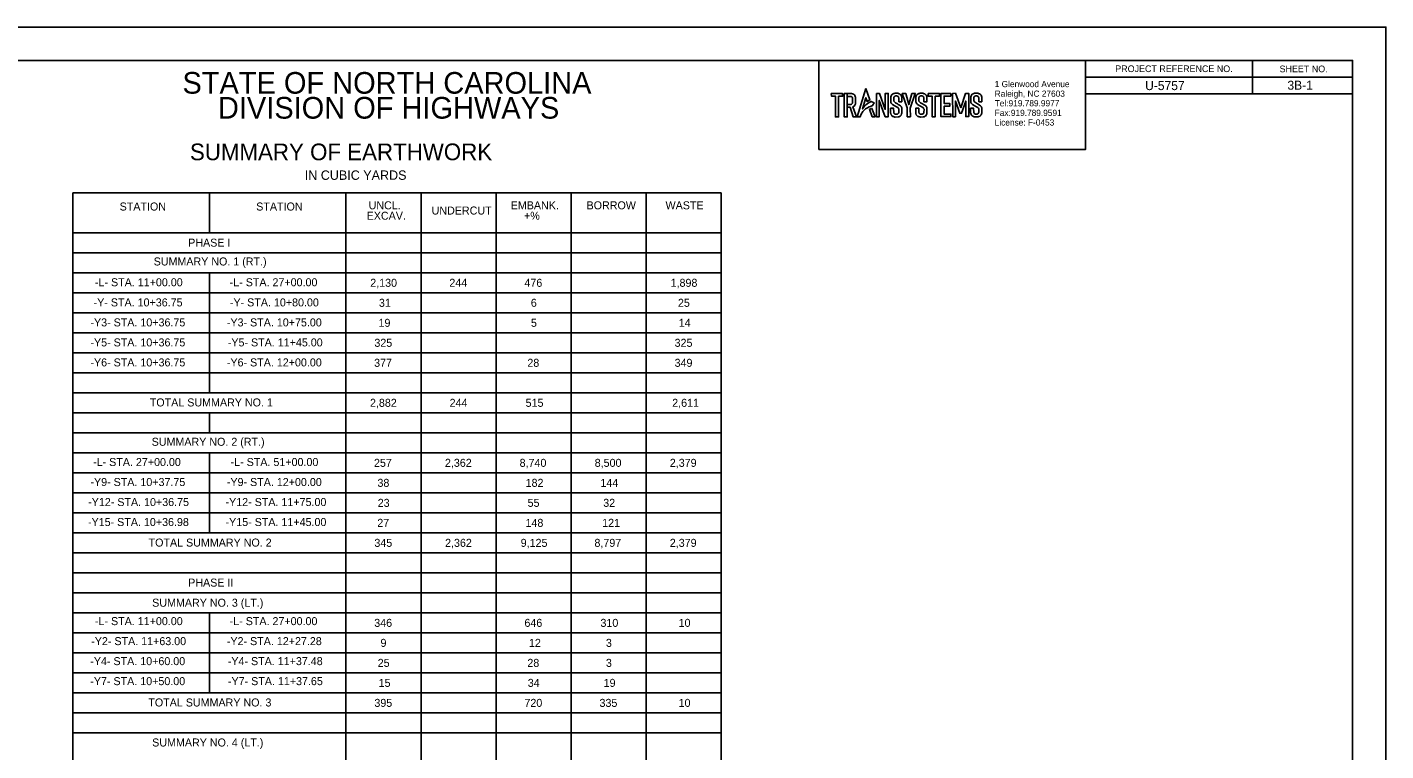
# Model space of a CAD drawing. Extents: x 573680 to 575380, y -53324 to -52224.
# Drawn here: x 574361 to 575380, y -52767 to -52224 of the extents above; entities that cross this region are included whole.
import ezdxf

# ---------------------------------------------------------------- set-up
doc = ezdxf.new("R2010")
doc.units = 0
for name, color, linetype in [('Old_Level_1', 7, 'Continuous'), ('Old_Level_2', 7, 'Continuous'), ('Old_Level_58', 7, 'Continuous'), ('Sheet Data Field CELL', 7, 'Continuous'), ('Sheet Plan And Profile CELL', 7, 'Continuous'), ('Sheet Plot Border Outside CELL', 7, 'Continuous'), ('Sheet Summary Combination CELL', 7, 'Continuous'), ('Sheet Summary Combination Grid CELL', 7, 'Continuous')]:
    doc.layers.add(name, color=color, linetype=linetype)

msp = doc.modelspace()

# ---------------------------------------------------------------- linework, layer by layer
at = {"layer": 'Old_Level_1'}
for points in [[(574964.1, -52274.1), (574972.6, -52274.1), (574972.6, -52276.1), (574969.5, -52276.1), (574969.5, -52291.6), (574967.2, -52291.6), (574967.2, -52276), (574964.2, -52276)], [(574973.8, -52274.1), (574976.1, -52274.1), (574976.1, -52291.6), (574973.8, -52291.6)], [(574976.1, -52276.2), (574978.5, -52276.2), (574978.8, -52276.2), (574979.2, -52276.4), (574979.5, -52276.6), (574979.7, -52276.9), (574979.9, -52277.2), (574980, -52277.5), (574980, -52278), (574980, -52280.5), (574980, -52280.9), (574979.9, -52281.3), (574979.7, -52281.6), (574979.5, -52281.9), (574979.3, -52282.1), (574978.9, -52282.2), (574978.5, -52282.3), (574978.2, -52282.3), (574976.1, -52282.3), (574976.1, -52284.4), (574978.2, -52284.4), (574980.6, -52291.6), (574983, -52291.5), (574980.3, -52284), (574980.7, -52283.9), (574981.3, -52283.5), (574981.7, -52282.9), (574982.1, -52282.3), (574982.3, -52281.7), (574982.3, -52281.5), (574982.3, -52276.9), (574982.1, -52276.2), (574981.8, -52275.5), (574981.4, -52275), (574980.7, -52274.6), (574980, -52274.3), (574979.3, -52274.1), (574978.9, -52274.1), (574976.1, -52274.1)], [(574990.1, -52270.2), (574983.4, -52291.6), (574985.7, -52291.6), (574986, -52290.7), (574986.6, -52289.6), (574986.9, -52288.9), (574987.3, -52288.4), (574987.8, -52287.6), (574988.1, -52287.2), (574988.5, -52286.8), (574988.9, -52286.4), (574989.4, -52285.9), (574989.8, -52285.6), (574990.2, -52285.3), (574990.8, -52285), (574991.2, -52284.7), (574992.5, -52284.1), (574993.5, -52283.7), (574995.1, -52283.1), (574996.2, -52281), (574994.1, -52280), (574992.4, -52280.9), (574991.1, -52281.8), (574990.1, -52282.6), (574989.6, -52283.1), (574989, -52283.6), (574988.5, -52284.2), (574988.1, -52284.6), (574987.7, -52285.3), (574987.5, -52285.6), (574990.1, -52277.2), (574991.1, -52280.1), (574993, -52278.9)], [(574997.9, -52274), (574997.9, -52291.5), (575000.1, -52291.5), (575000.1, -52279.2), (575004.6, -52291.5), (575006.8, -52291.5), (575006.8, -52274), (575004.6, -52274), (575004.6, -52286), (575000.2, -52274)], [(575014.6, -52280.2), (575016.9, -52280.2), (575016.9, -52276.7), (575016.7, -52276), (575016.4, -52275.4), (575016.1, -52275.1), (575015.7, -52274.7), (575015.3, -52274.4), (575014.9, -52274.2), (575014.9, -52274.2), (575014.4, -52274), (575013.9, -52273.9), (575013.6, -52273.8), (575011.9, -52273.9), (575011.3, -52274), (575010.9, -52274.1), (575010.4, -52274.3), (575010, -52274.5), (575009.6, -52274.8), (575009.3, -52275.1), (575009.1, -52275.5), (575008.9, -52275.9), (575008.6, -52276.6), (575008.6, -52277.1), (575008.6, -52280.2), (575008.7, -52280.7), (575008.9, -52281.2), (575009.2, -52281.6), (575009.5, -52281.9), (575009.9, -52282.3), (575010.4, -52282.6), (575010.7, -52282.8), (575011.2, -52283.1), (575011.7, -52283.3), (575012, -52283.6), (575012.5, -52283.8), (575013, -52284.1), (575013.4, -52284.3), (575013.9, -52284.6), (575014.2, -52284.9), (575014.4, -52285.2), (575014.6, -52285.7), (575014.7, -52286), (575014.6, -52288.2), (575014.5, -52288.7), (575014.2, -52289.1), (575013.9, -52289.4), (575013.6, -52289.5), (575013.2, -52289.6), (575012.3, -52289.6), (575011.9, -52289.5), (575011.6, -52289.4), (575011.3, -52289.2), (575011.1, -52288.8), (575011, -52288.5), (575010.9, -52288.2), (575010.8, -52285.1), (575008.5, -52285.1), (575008.5, -52288.8), (575008.7, -52289.1), (575008.9, -52290), (575009.1, -52290.3), (575009.4, -52290.6), (575009.7, -52291), (575010, -52291.2), (575010.5, -52291.4), (575010.6, -52291.4), (575011.1, -52291.6), (575011.6, -52291.7), (575012, -52291.7), (575014.1, -52291.6), (575014.7, -52291.5), (575015.6, -52291.1), (575015.8, -52291), (575016.5, -52290.2), (575016.8, -52289.4), (575016.9, -52288.7), (575016.9, -52285.3), (575016.9, -52284.8), (575016.8, -52284.4), (575016.6, -52284.1), (575016, -52283.3), (575015.3, -52282.8), (575014.3, -52282.2), (575013.6, -52281.7), (575012.1, -52281), (575011.4, -52280.4), (575011.1, -52280), (575011, -52279.7), (575010.9, -52279.4), (575010.9, -52277), (575011.1, -52276.7), (575011.2, -52276.5), (575011.4, -52276.3), (575011.6, -52276.1), (575011.9, -52276), (575012.1, -52275.9), (575012.3, -52276), (575012.3, -52275.9), (575013.2, -52275.9), (575013.5, -52276), (575013.8, -52276.1), (575014.1, -52276.2), (575014.2, -52276.4), (575014.4, -52276.7), (575014.5, -52277), (575014.6, -52277.2), (575014.6, -52277.6)], [(575019.9, -52274), (575017.3, -52274), (575020.9, -52284.9), (575021, -52291.5), (575023.4, -52291.5), (575023.3, -52285), (575027, -52274), (575024.5, -52274.1), (575022.2, -52282.4)], [(575033.5, -52280.2), (575035.8, -52280.2), (575035.8, -52276.7), (575035.6, -52276), (575035.3, -52275.4), (575035, -52275), (575034.6, -52274.7), (575034.2, -52274.4), (575033.7, -52274.2), (575033.7, -52274.2), (575033.3, -52274), (575032.8, -52273.9), (575032.5, -52273.8), (575030.7, -52273.9), (575030.2, -52274), (575029.8, -52274), (575029.3, -52274.3), (575028.9, -52274.5), (575028.5, -52274.8), (575028.2, -52275.1), (575027.9, -52275.4), (575027.7, -52275.8), (575027.5, -52276.5), (575027.4, -52277.1), (575027.4, -52280.2), (575027.6, -52280.7), (575027.8, -52281.2), (575028.1, -52281.6), (575028.4, -52281.9), (575028.8, -52282.3), (575029.3, -52282.6), (575029.6, -52282.8), (575030, -52283.1), (575030.5, -52283.3), (575030.9, -52283.5), (575031.4, -52283.8), (575031.9, -52284.1), (575032.3, -52284.3), (575032.7, -52284.6), (575033.1, -52284.9), (575033.3, -52285.2), (575033.5, -52285.6), (575033.6, -52285.9), (575033.5, -52288.2), (575033.4, -52288.7), (575033.1, -52289.1), (575032.8, -52289.4), (575032.4, -52289.5), (575032.1, -52289.6), (575031.1, -52289.6), (575030.8, -52289.5), (575030.5, -52289.3), (575030.1, -52289.1), (575030, -52288.8), (575029.9, -52288.5), (575029.7, -52288.2), (575029.7, -52285.1), (575027.4, -52285.1), (575027.4, -52288.8), (575027.5, -52289.1), (575027.8, -52290), (575028, -52290.3), (575028.2, -52290.6), (575028.6, -52291), (575028.9, -52291.2), (575029.4, -52291.3), (575029.5, -52291.4), (575029.9, -52291.6), (575030.5, -52291.6), (575030.9, -52291.7), (575033, -52291.6), (575033.6, -52291.5), (575034.4, -52291.1), (575034.7, -52291), (575035.3, -52290.2), (575035.7, -52289.4), (575035.8, -52288.7), (575035.8, -52285.3), (575035.8, -52284.8), (575035.6, -52284.4), (575035.4, -52284.1), (575034.9, -52283.3), (575034.2, -52282.8), (575033.2, -52282.2), (575032.5, -52281.7), (575031, -52281), (575030.3, -52280.4), (575029.9, -52280), (575029.8, -52279.7), (575029.8, -52279.4), (575029.8, -52277), (575029.9, -52276.7), (575030.1, -52276.5), (575030.2, -52276.3), (575030.5, -52276.1), (575030.7, -52276), (575031, -52275.9), (575031.1, -52275.9), (575031.2, -52275.9), (575032.1, -52275.9), (575032.4, -52276), (575032.7, -52276.1), (575032.9, -52276.2), (575033.1, -52276.4), (575033.3, -52276.7), (575033.4, -52277), (575033.4, -52277.2), (575033.4, -52277.5)], [(575036.6, -52274), (575045.1, -52274), (575045.1, -52276.1), (575042, -52276.1), (575042, -52291.5), (575039.6, -52291.5), (575039.6, -52276), (575036.6, -52276)], [(575053.7, -52274), (575046.3, -52274), (575046.3, -52291.4), (575053.8, -52291.4), (575053.8, -52289.5), (575048.7, -52289.5), (575048.7, -52283.6), (575052.9, -52283.6), (575052.9, -52281.5), (575048.7, -52281.5), (575048.7, -52276), (575053.7, -52276)], [(575061.1, -52284.9), (575057.2, -52273.9), (575055, -52274), (575055.1, -52291.5), (575057.2, -52291.5), (575057.2, -52279.8), (575060.4, -52288.8), (575061.8, -52288.8), (575064.9, -52279.7), (575064.9, -52291.4), (575067.2, -52291.4), (575067.1, -52274), (575064.8, -52274)], [(575074.6, -52280.2), (575076.9, -52280.2), (575076.9, -52276.7), (575076.7, -52276), (575076.4, -52275.4), (575076.1, -52275), (575075.7, -52274.6), (575075.3, -52274.4), (575074.9, -52274.2), (575074.9, -52274.2), (575074.4, -52274), (575073.9, -52273.9), (575073.6, -52273.8), (575071.9, -52273.8), (575071.3, -52273.9), (575070.9, -52274), (575070.4, -52274.2), (575070, -52274.4), (575069.6, -52274.7), (575069.3, -52275), (575069.1, -52275.4), (575068.9, -52275.8), (575068.6, -52276.5), (575068.6, -52277), (575068.6, -52280.2), (575068.7, -52280.7), (575068.9, -52281.2), (575069.2, -52281.6), (575069.5, -52281.9), (575070, -52282.2), (575070.4, -52282.6), (575070.7, -52282.8), (575071.2, -52283), (575071.7, -52283.2), (575072, -52283.5), (575072.5, -52283.8), (575073, -52284), (575073.4, -52284.3), (575073.9, -52284.6), (575074.2, -52284.9), (575074.4, -52285.1), (575074.6, -52285.6), (575074.7, -52285.9), (575074.7, -52288.1), (575074.5, -52288.6), (575074.2, -52289), (575073.9, -52289.3), (575073.6, -52289.5), (575073.2, -52289.6), (575072.3, -52289.6), (575071.9, -52289.5), (575071.6, -52289.3), (575071.3, -52289.1), (575071.1, -52288.8), (575071, -52288.4), (575070.9, -52288.2), (575070.8, -52285.1), (575068.5, -52285.1), (575068.5, -52288.8), (575068.7, -52289.1), (575068.9, -52289.9), (575069.1, -52290.2), (575069.4, -52290.5), (575069.7, -52290.9), (575070.1, -52291.1), (575070.5, -52291.3), (575070.6, -52291.4), (575071.1, -52291.5), (575071.6, -52291.6), (575072, -52291.6), (575074.1, -52291.6), (575074.7, -52291.4), (575075.6, -52291.1), (575075.8, -52290.9), (575076.5, -52290.1), (575076.8, -52289.4), (575077, -52288.7), (575076.9, -52285.2), (575076.9, -52284.8), (575076.8, -52284.4), (575076.6, -52284), (575076, -52283.3), (575075.3, -52282.7), (575074.3, -52282.1), (575073.6, -52281.7), (575072.1, -52280.9), (575071.4, -52280.4), (575071.1, -52279.9), (575071, -52279.7), (575070.9, -52279.4), (575070.9, -52276.9), (575071.1, -52276.7), (575071.2, -52276.4), (575071.4, -52276.3), (575071.6, -52276.1), (575071.9, -52276), (575072.1, -52275.9), (575072.3, -52275.9), (575072.3, -52275.8), (575073.2, -52275.8), (575073.5, -52275.9), (575073.8, -52276.1), (575074.1, -52276.2), (575074.2, -52276.4), (575074.4, -52276.6), (575074.5, -52276.9), (575074.6, -52277.2), (575074.6, -52277.5)], [(574992.7, -52285.9), (574994.6, -52285.2), (574996.9, -52291.6), (574994.8, -52291.5)]]:
    msp.add_lwpolyline(points, close=True, dxfattribs=at)
at = {"layer": 'Old_Level_58'}
msp.add_lwpolyline([(574954.8, -52249.3), (575154.8, -52249.3), (575154.8, -52316), (574954.8, -52316)], close=True, dxfattribs=at)
at = {"layer": 'Sheet Plan And Profile CELL'}
for points in [[(575354.9, -52249.3), (573854.9, -52249.3), (573854.9, -53299.3), (575354.9, -53299.3)], [(575154.8, -52249.3), (575354.9, -52249.3), (575354.9, -52274.4), (575154.8, -52274.4)]]:
    msp.add_lwpolyline(points, close=True, dxfattribs=at)
at = {"layer": 'Sheet Plot Border Outside CELL'}
msp.add_lwpolyline([(573679.9, -53324.3), (575379.9, -53324.3), (575379.9, -52224.3), (573679.9, -52224.3)], close=True, dxfattribs=at)
at = {"layer": 'Sheet Summary Combination CELL'}
for p, q in [((575279.9, -52249.4), (575279.9, -52274.4)), ((575154.8, -52261.9), (575354.9, -52261.9)), ((575154.8, -52274.4), (575354.9, -52274.4)), ((574526.7, -52348.5), (574526.7, -52348.5)), ((574534.2, -52348.6), (574534.2, -52348.6)), ((574545, -52348.4), (574545, -52348.4)), ((574551.7, -52348.5), (574551.7, -52348.5))]:
    msp.add_line(p, q, dxfattribs=at)
msp.add_lwpolyline([(575154.8, -52249.3), (575354.9, -52249.3), (575354.9, -52274.4), (575154.8, -52274.4)], close=True, dxfattribs=at)
at = {"layer": 'Sheet Summary Combination Grid CELL'}
for p, q in [((574395.4, -52348.5), (574881.6, -52348.5)), ((574395.4, -52348.5), (574395.4, -53023.5)), ((574497.9, -52348.5), (574497.9, -52378.5)), ((574600.2, -52348.5), (574600.2, -53023.5)), ((574656.5, -52348.5), (574656.5, -53023.5)), ((574712.8, -52348.5), (574712.8, -53023.5)), ((574769.1, -52348.5), (574769.1, -53023.5)), ((574825.3, -52348.5), (574825.3, -53023.5)), ((574881.6, -52348.5), (574881.6, -53023.5)), ((574395.4, -52378.5), (574881.6, -52378.5)), ((574395.4, -52393.5), (574881.6, -52393.5)), ((574395.4, -52408.5), (574881.6, -52408.5)), ((574497.9, -52408.6), (574497.9, -52498.5)), ((574395.4, -52423.5), (574881.6, -52423.5)), ((574395.4, -52438.5), (574881.6, -52438.5)), ((574395.4, -52453.5), (574881.6, -52453.5)), ((574395.4, -52468.5), (574881.6, -52468.5)), ((574395.4, -52483.5), (574881.6, -52483.5)), ((574395.4, -52498.5), (574881.6, -52498.5)), ((574395.4, -52513.5), (574881.6, -52513.5)), ((574497.9, -52513.5), (574497.9, -52528.5)), ((574395.4, -52528.5), (574881.6, -52528.5)), ((574395.4, -52543.5), (574881.6, -52543.5)), ((574497.9, -52543.5), (574497.9, -52603.5)), ((574395.4, -52558.5), (574881.6, -52558.5)), ((574395.4, -52573.5), (574881.6, -52573.5)), ((574395.4, -52588.5), (574881.6, -52588.5)), ((574395.4, -52603.5), (574881.6, -52603.5)), ((574395.4, -52618.5), (574881.6, -52618.5)), ((574395.4, -52633.5), (574881.6, -52633.5)), ((574395.4, -52648.5), (574881.6, -52648.5)), ((574395.4, -52663.5), (574881.6, -52663.5)), ((574497.9, -52663.5), (574497.9, -52723.5)), ((574395.4, -52678.5), (574881.6, -52678.5)), ((574395.4, -52693.5), (574881.6, -52693.5)), ((574395.4, -52708.5), (574881.6, -52708.5)), ((574395.4, -52723.5), (574881.6, -52723.5)), ((574395.4, -52738.5), (574881.6, -52738.5)), ((574395.4, -52738.5), (574881.6, -52738.5)), ((574395.4, -52753.5), (574881.6, -52753.5))]:
    msp.add_line(p, q, dxfattribs=at)

# ---------------------------------------------------------------- texts
at = {"layer": 'Old_Level_2'}
for s, p in [('1 Glenwood Avenue', (575086.6, -52269.3)), ('Tel:919.789.9977 ', (575086.6, -52283.7)), ('Raleigh, NC 27603', (575086.6, -52276.5)), ('Fax:919.789.9591', (575086.6, -52290.9)), ('License: F-0453', (575086.6, -52298.1))]:
    msp.add_text(s, height=4.658, rotation=360, dxfattribs=at).set_placement(p)
at = {"layer": 'Sheet Data Field CELL'}
for s, p in [('U-5757', (575199.4, -52271.5)), ('3B-1', (575306.1, -52271.2))]:
    msp.add_text(s, height=6.75, dxfattribs=at).set_placement(p)
at = {"layer": 'Sheet Plan And Profile CELL'}
for s, p in [('PROJECT REFERENCE NO.', (575177, -52258)), ('SHEET NO.', (575300.2, -52258.1))]:
    msp.add_text(s, height=5, rotation=360, dxfattribs=at).set_placement(p)
at = {"layer": 'Sheet Summary Combination CELL'}
for s, height, p in [('STATE OF NORTH CAROLINA', 16.25, (574477.6, -52274.2)), ('PROJECT REFERENCE NO.', 5, (575177, -52258)), ('SHEET NO.', 5, (575300.2, -52258.1)), ('DIVISION OF HIGHWAYS', 16.25, (574504.2, -52292.9)), ('STATION', 6, (574430.5, -52361.8)), ('STATION', 6, (574532.9, -52361.8)), ('UNCL.', 6, (574617.2, -52360.9)), ('UNDERCUT', 6, (574664.4, -52364.8)), ('EMBANK.', 6, (574723.7, -52360.9)), ('BORROW', 6, (574780.6, -52360.9)), ('WASTE', 6, (574839.8, -52360.9)), ('EXCAV.', 6, (574615.7, -52368.7)), ('+%', 6, (574733.7, -52368.7)), ('PHASE I', 6, (574481.9, -52388.9)), ('SUMMARY NO. 1 (RT.)', 6, (574456, -52403)), ('-L- STA. 11+00.00', 6, (574412, -52418.6)), ('-L- STA. 27+00.00', 6, (574513, -52418.6)), ('2,130', 6, (574618.4, -52419)), ('244', 6, (574677.7, -52419)), ('476', 6, (574734, -52419)), ('1,898', 6, (574843.6, -52419)), ('-Y- STA. 10+36.75', 6, (574411, -52433.7)), ('-Y- STA. 10+80.00', 6, (574513.2, -52433.7)), ('31', 6, (574624.9, -52434)), ('6', 6, (574738.8, -52434)), ('25', 6, (574849.1, -52434)), ('-Y3- STA. 10+36.75', 6, (574408.6, -52448.7)), ('-Y3- STA. 10+75.00', 6, (574510.9, -52448.7)), ('19', 6, (574624.6, -52449)), ('5', 6, (574738.9, -52449)), ('14', 6, (574849.7, -52449)), ('-Y5- STA. 10+36.75', 6, (574408.6, -52463.7)), ('-Y5- STA. 11+45.00', 6, (574511.6, -52463.7)), ('325', 6, (574621.5, -52464)), ('325', 6, (574846.6, -52464)), ('-Y6- STA. 10+36.75', 6, (574408.6, -52478.7)), ('-Y6- STA. 12+00.00', 6, (574510.9, -52478.7)), ('377', 6, (574621.3, -52479)), ('28', 6, (574736.2, -52479)), ('349', 6, (574846.6, -52479)), ('TOTAL SUMMARY NO. 1', 6, (574453.1, -52508.7)), ('2,882', 6, (574618.2, -52509)), ('244', 6, (574677.9, -52509)), ('515', 6, (574734.9, -52509)), ('2,611', 6, (574844.8, -52509)), ('SUMMARY NO. 2 (RT.)', 6, (574454.5, -52538.2)), ('-L- STA. 27+00.00', 6, (574410.6, -52553.4)), ('-L- STA. 51+00.00', 6, (574513.7, -52553.4)), ('257', 6, (574621.2, -52554)), ('2,362', 6, (574674.4, -52554)), ('8,740', 6, (574730.4, -52554)), ('8,500', 6, (574786.7, -52554)), ('2,379', 6, (574843, -52554)), ('-Y9- STA. 10+37.75', 6, (574408.6, -52568.4)), ('-Y9- STA. 12+00.00', 6, (574510.9, -52568.4)), ('38', 6, (574623.8, -52569)), ('182', 6, (574734.9, -52569)), ('144', 6, (574791, -52569)), ('-Y12- STA. 10+36.75', 6, (574406.9, -52583.4)), ('-Y12- STA. 11+75.00', 6, (574509.9, -52583.4)), ('23', 6, (574624, -52584)), ('55', 6, (574736.4, -52584)), ('32', 6, (574793.1, -52584)), ('-Y15- STA. 10+36.98', 6, (574406.8, -52598.4)), ('-Y15- STA. 11+45.00', 6, (574509.9, -52598.4)), ('27', 6, (574623.7, -52599)), ('148', 6, (574734.8, -52599)), ('121', 6, (574792.3, -52599)), ('TOTAL SUMMARY NO. 2', 6, (574452.2, -52613.8)), ('345', 6, (574621.5, -52614)), ('2,362', 6, (574674.5, -52614)), ('9,125', 6, (574731.2, -52614)), ('8,797', 6, (574786.5, -52614)), ('2,379', 6, (574843, -52614)), ('PHASE II', 6, (574481.9, -52643.8)), ('SUMMARY NO. 3 (LT.)', 6, (574454.9, -52658.9)), ('-L- STA. 11+00.00', 6, (574412, -52672.7)), ('-L- STA. 27+00.00', 6, (574513, -52672.7)), ('346', 6, (574621.4, -52674)), ('646', 6, (574734, -52674)), ('310', 6, (574791, -52674)), ('10', 6, (574849.6, -52674)), ('-Y2- STA. 11+63.00', 6, (574409.2, -52687.7)), ('-Y2- STA. 12+27.28', 6, (574510.9, -52687.7)), ('9', 6, (574626.1, -52689)), ('12', 6, (574737.4, -52689)), ('3', 6, (574795.1, -52689)), ('-Y4- STA. 10+60.00', 6, (574408.5, -52702.7)), ('-Y4- STA. 11+37.48', 6, (574511.6, -52702.7)), ('25', 6, (574624, -52704)), ('28', 6, (574736.2, -52704)), ('3', 6, (574795.1, -52704)), ('-Y7- STA. 10+50.00', 6, (574408.5, -52717.7)), ('-Y7- STA. 11+37.65', 6, (574511.7, -52717.7)), ('15', 6, (574624.7, -52719)), ('34', 6, (574736.5, -52719)), ('19', 6, (574793.4, -52719)), ('TOTAL SUMMARY NO. 3', 6, (574452, -52733.7)), ('395', 6, (574621.5, -52734)), ('720', 6, (574734, -52734)), ('335', 6, (574790.3, -52734)), ('10', 6, (574849.6, -52734)), ('SUMMARY NO. 4 (LT.)', 6, (574454.9, -52763.7))]:
    msp.add_text(s, height=height, dxfattribs=at).set_placement(p)
for s, height, p in [('SUMMARY OF EARTHWORK', 12.5, (574483.2, -52324.1)), ('IN CUBIC YARDS', 7.031, (574569.3, -52338.8))]:
    msp.add_text(s, height=height, rotation=0.0119, dxfattribs=at).set_placement(p)

doc.saveas('drawing.dxf')
